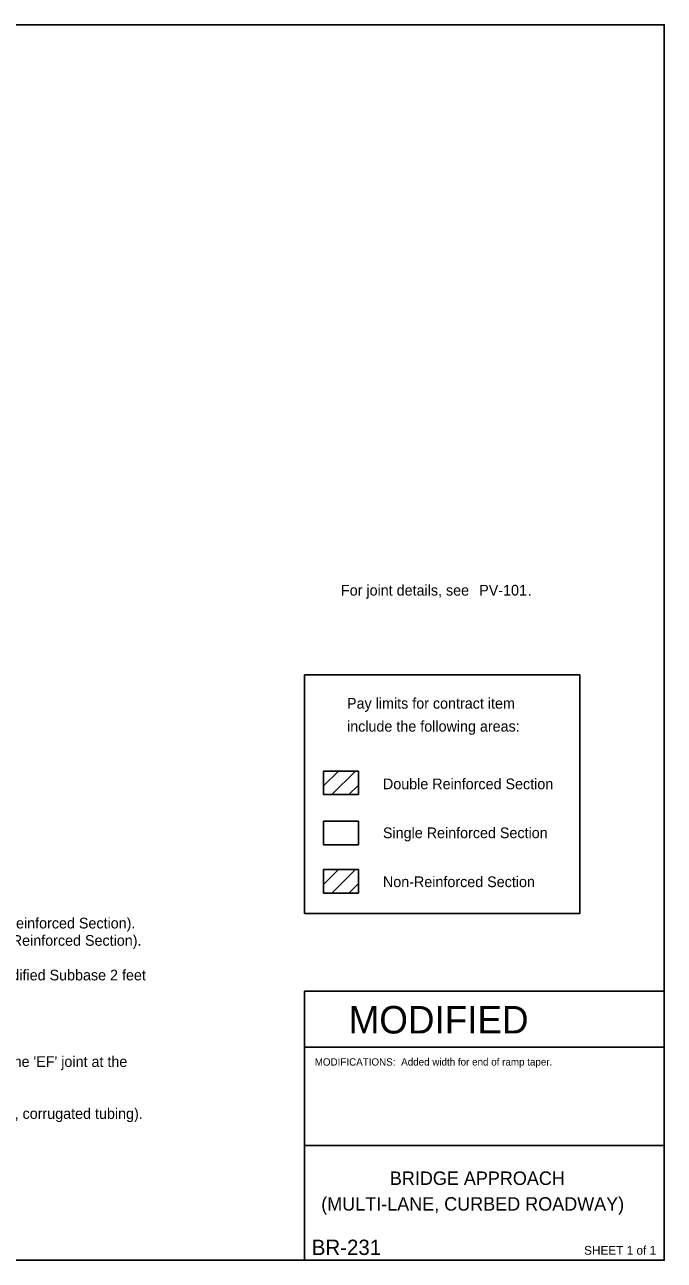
# Model space of a CAD drawing. Extents: x 10133 to 81668, y 7924 to 11018.
# Drawn here: x 12222 to 13268, y 7924 to 9944 of the extents above; entities that cross this region are included whole.
import ezdxf

# ---------------------------------------------------------------- set-up
doc = ezdxf.new("R2010")
doc.units = 0
for name, color, linetype in [('BridgeExistingStructure', 7, 'Continuous'), ('DisCLMLORPoints', 7, 'Continuous'), ('dsnAlignmentStation', 7, 'Continuous'), ('RasterAttachment', 7, 'Continuous'), ('SheetBorder', 7, 'Continuous')]:
    doc.layers.add(name, color=color, linetype=linetype)

msp = doc.modelspace()

# ---------------------------------------------------------------- linework, layer by layer
at = {"layer": 'BridgeExistingStructure'}
for p, q in [((12710.6, 8723.9), (12767.5, 8723.9)), ((12710.6, 8685.4), (12710.6, 8723.9)), ((12767.5, 8723.9), (12767.5, 8685.4)), ((12767.5, 8685.4), (12710.6, 8685.4)), ((12710.6, 8641.9), (12767.5, 8641.9)), ((12710.6, 8603.4), (12710.6, 8641.9)), ((12767.5, 8641.9), (12767.5, 8603.4)), ((12767.5, 8603.4), (12710.6, 8603.4))]:
    msp.add_line(p, q, dxfattribs=at)
at = {"layer": 'DisCLMLORPoints'}
for p, q in [((12679.5, 8272.7), (13267.5, 8272.7)), ((12679.5, 8111.6), (13267.5, 8111.6))]:
    msp.add_line(p, q, dxfattribs=at)
msp.add_lwpolyline([(12679.5, 8364), (13267.5, 8364), (13267.5, 7924), (12679.5, 7924)], close=True, dxfattribs=at)
at = {"layer": 'RasterAttachment'}
for p, q in [((12710.6, 8723.9), (12767.5, 8723.9)), ((12710.6, 8723.9), (12710.6, 8685.4)), ((12710.6, 8699.5), (12735.1, 8723.9)), ((12724.2, 8685.4), (12762.8, 8723.9)), ((12767.5, 8723.9), (12767.5, 8685.4)), ((12751.9, 8685.4), (12767.5, 8701)), ((12767.5, 8685.4), (12710.6, 8685.4)), ((12710.6, 8641.9), (12767.5, 8641.9)), ((12710.6, 8641.9), (12710.6, 8603.4)), ((12767.5, 8641.9), (12767.5, 8603.4)), ((12767.5, 8603.4), (12710.6, 8603.4)), ((12710.6, 8538.5), (12735.1, 8562.9)), ((12724.2, 8524.4), (12762.8, 8562.9)), ((12751.9, 8524.4), (12767.5, 8540))]:
    msp.add_line(p, q, dxfattribs=at)
for points in [[(12679.5, 8881.1), (13129.6, 8881.1), (13129.6, 8491.2), (12679.5, 8491.2)], [(12710.6, 8562.9), (12767.5, 8562.9), (12767.5, 8524.4), (12710.6, 8524.4)]]:
    msp.add_lwpolyline(points, close=True, dxfattribs=at)
at = {"layer": 'SheetBorder'}
msp.add_lwpolyline([(10132.5, 9944), (13267.5, 9944), (13267.5, 7924), (10132.5, 7924)], close=True, dxfattribs=at)

# ---------------------------------------------------------------- texts
at = {"layer": 'BridgeExistingStructure'}
for s, p in [('For joint details, see ', (12739, 9010.7)), ('PV-101', (12965, 9010.7)), ('PV-101', (12965, 9010.7)), ('.', (13044.3, 9010.7)), ('Pay limits for contract item', (12748.9, 8825.8)), ('include the following areas:', (12748.9, 8788.3)), ('Double Reinforced Section', (12807.6, 8694.1)), ('Single Reinforced Section', (12807.6, 8614.1)), ('Non-Reinforced Section', (12807.6, 8534.1)), ("     Two Pours -  Use 'KS-1' joint (Single Reinforced Section).", (11774.9, 8466.5)), ("     Use 'KS-2' joint (Double Reinforced Section).", (11914.9, 8438.2)), ('Polymer Grid and excavation limits of Modified Subbase 2 feet ', (11774.9, 8381.6)), ('Place an "X" in the plastic concrete near the \'EF\' joint at the ', (11774.9, 8240.1)), ('4 inch perforated subdrain (polyetheylene, corrugated tubing).', (11774.9, 8155.2))]:
    msp.add_text(s, height=17.5, dxfattribs=at).set_placement(p)
at = {"layer": 'DisCLMLORPoints'}
for s, height, p in [('Added width for end of ramp taper.', 12, (12837.4, 8242.4)), ('BRIDGE APPROACH', 22, (12818.9, 8047.2)), ('(MULTI-LANE, CURBED ROADWAY)', 22, (12706.7, 8005.2)), ('BR-231', 25, (12691.3, 7932.7))]:
    msp.add_text(s, height=height, dxfattribs=at).set_placement(p)
at = {"layer": 'dsnAlignmentStation'}
for s, height, p in [('MODIFIED', 45, (12751.5, 8294.8)), ('MODIFICATIONS:', 12, (12696.1, 8242.3)), ('SHEET 1 of 1', 14.4, (13136.5, 7933.1))]:
    msp.add_text(s, height=height, dxfattribs=at).set_placement(p)

doc.saveas('drawing.dxf')
